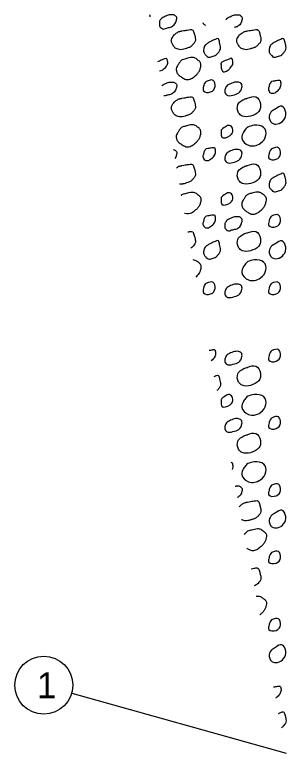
# Model space of a CAD drawing. Extents: x 0 to 340, y 0 to 220.
# Drawn here: x 135.85 to 150.51, y 109.99 to 149.82 of the extents above; entities that cross this region are included whole.
import ezdxf

# ---------------------------------------------------------------- set-up
doc = ezdxf.new("R2010")
doc.units = 0
for name, color, linetype in [('GE_P_Alignment_100_Stations', 7, 'Continuous'), ('MT_P_Work_Area', 7, 'Continuous'), ('SC_Scratch1', 7, 'Continuous')]:
    doc.layers.add(name, color=color, linetype=linetype)

msp = doc.modelspace()

# ---------------------------------------------------------------- linework, layer by layer
at = {"layer": 'GE_P_Alignment_100_Stations'}
msp.add_line((138.923, 113.234), (150.509, 109.987), dxfattribs=at)
at = {"layer": 'MT_P_Work_Area'}
msp.add_circle((137.414, 113.657), 1.567, dxfattribs=at)
at = {"layer": 'SC_Scratch1'}
for points, degree in [([(143.128, 149.812), (143.137, 149.782), (143.143, 149.748), (143.145, 149.715)], 2), ([(143.783, 149.635), (143.866, 149.676), (143.949, 149.718), (144.033, 149.76), (144.124, 149.805), (144.234, 149.814), (144.334, 149.817), (144.407, 149.819), (144.478, 149.802), (144.545, 149.736), (144.605, 149.676), (144.596, 149.596), (144.579, 149.533), (144.549, 149.428), (144.51, 149.321), (144.408, 149.236), (144.308, 149.153), (144.202, 149.141), (144.095, 149.116), (143.982, 149.09), (143.853, 149.023), (143.743, 149.122), (143.67, 149.187), (143.655, 149.263), (143.657, 149.338), (143.659, 149.404), (143.667, 149.483), (143.709, 149.538), (143.733, 149.571), (143.758, 149.602), (143.783, 149.635)], 3), ([(147.319, 149.635), (147.402, 149.676), (147.485, 149.718), (147.569, 149.76), (147.66, 149.805), (147.77, 149.814), (147.87, 149.817), (147.943, 149.819), (148.014, 149.802), (148.08, 149.736), (148.141, 149.676), (148.132, 149.596), (148.115, 149.533), (148.085, 149.428), (148.046, 149.321), (147.944, 149.236), (147.863, 149.169), (147.779, 149.148), (147.692, 149.13)], 3), ([(146.16, 149.248), (146.107, 149.265), (146.063, 149.295), (146.04, 149.341), (146.034, 149.355), (146.029, 149.369), (146.025, 149.383)], 3), ([(147.262, 149.561), (147.281, 149.585), (147.3, 149.61), (147.319, 149.635)], 2), ([(144.87, 148.945), (145.021, 148.971), (145.172, 149), (145.324, 149.021), (145.475, 149.042), (145.545, 148.783), (145.583, 148.641), (145.617, 148.512), (145.595, 148.355), (145.486, 148.235), (145.353, 148.087), (145.205, 148.03), (145.04, 147.982), (144.899, 147.941), (144.741, 147.925), (144.6, 147.985), (144.515, 148.021), (144.453, 148.083), (144.401, 148.163), (144.315, 148.297), (144.289, 148.481), (144.365, 148.608), (144.415, 148.692), (144.482, 148.766), (144.57, 148.821), (144.643, 148.868), (144.714, 148.912), (144.795, 148.93), (144.823, 148.935), (144.85, 148.941), (144.878, 148.947)], 3), ([(148.405, 148.945), (148.557, 148.971), (148.708, 149), (148.86, 149.021), (149.011, 149.042), (149.081, 148.783), (149.119, 148.641), (149.153, 148.512), (149.131, 148.355), (149.022, 148.235), (148.889, 148.087), (148.741, 148.03), (148.576, 147.982), (148.435, 147.941), (148.277, 147.925), (148.136, 147.985), (148.051, 148.021), (147.989, 148.083), (147.937, 148.163), (147.851, 148.297), (147.825, 148.481), (147.9, 148.608), (147.95, 148.692), (148.018, 148.766), (148.105, 148.821), (148.179, 148.868), (148.25, 148.912), (148.331, 148.93), (148.359, 148.935), (148.386, 148.941), (148.414, 148.947)], 3), ([(146.385, 148.363), (146.503, 148.413), (146.62, 148.463), (146.737, 148.514), (146.859, 148.566), (146.918, 148.299), (146.945, 148.175), (146.973, 148.044), (146.939, 147.897), (146.833, 147.77), (146.733, 147.651), (146.619, 147.594), (146.5, 147.558), (146.404, 147.529), (146.283, 147.524), (146.189, 147.617), (146.075, 147.73), (146.033, 147.862), (146.055, 147.976), (146.074, 148.067), (146.116, 148.187), (146.201, 148.244), (146.263, 148.284), (146.324, 148.323), (146.385, 148.363)], 3), ([(149.921, 148.363), (150.038, 148.413), (150.156, 148.463), (150.273, 148.514), (150.394, 148.566), (150.454, 148.299), (150.48, 148.175), (150.509, 148.044), (150.475, 147.897), (150.369, 147.77), (150.269, 147.651), (150.155, 147.594), (150.035, 147.558), (149.939, 147.529), (149.818, 147.524), (149.725, 147.617), (149.611, 147.73), (149.568, 147.862), (149.591, 147.976), (149.609, 148.067), (149.652, 148.187), (149.737, 148.244), (149.798, 148.284), (149.86, 148.323), (149.921, 148.363)], 3), ([(143.571, 147.3), (143.703, 147.355), (143.834, 147.41), (143.966, 147.46), (144.044, 147.49), (144.085, 147.316), (144.092, 147.242), (144.101, 147.142), (144.025, 147.038), (143.943, 146.94), (143.88, 146.864), (143.762, 146.799), (143.662, 146.785)], 3), ([(144.89, 147.394), (145.009, 147.425), (145.128, 147.456), (145.246, 147.487), (145.419, 147.532), (145.594, 147.5), (145.767, 147.355), (145.901, 147.243), (145.91, 147.077), (145.875, 146.953), (145.83, 146.796), (145.731, 146.648), (145.579, 146.518), (145.389, 146.356), (145.125, 146.292), (144.93, 146.407), (144.773, 146.5), (144.607, 146.64), (144.576, 146.805), (144.557, 146.908), (144.611, 147.028), (144.671, 147.124), (144.714, 147.192), (144.753, 147.261), (144.81, 147.316), (144.836, 147.342), (144.863, 147.368), (144.89, 147.394)], 3), ([(147.027, 147.268), (147.185, 147.332), (147.344, 147.4), (147.502, 147.46), (147.58, 147.49), (147.621, 147.316), (147.628, 147.242), (147.637, 147.142), (147.561, 147.038), (147.479, 146.94), (147.367, 146.805), (147.087, 146.708), (147.029, 146.855), (146.998, 146.934), (146.993, 147.014), (146.99, 147.095), (146.988, 147.136), (146.973, 147.18), (146.994, 147.216), (147.004, 147.235), (147.016, 147.251), (147.027, 147.268)], 3), ([(143.798, 146.012), (143.876, 146.051), (143.954, 146.09), (144.033, 146.129), (144.124, 146.175), (144.234, 146.184), (144.334, 146.187), (144.407, 146.189), (144.478, 146.171), (144.545, 146.106), (144.605, 146.046), (144.596, 145.966), (144.579, 145.902), (144.549, 145.797), (144.51, 145.691), (144.408, 145.606), (144.308, 145.523), (144.202, 145.511), (144.095, 145.486), (144.032, 145.471), (143.965, 145.444), (143.899, 145.44)], 3), ([(149.717, 146.221), (149.844, 146.239), (149.971, 146.259), (150.099, 146.277), (150.212, 146.292), (150.239, 146.047), (150.203, 145.948), (150.163, 145.84), (150.065, 145.732), (149.963, 145.654), (149.858, 145.574), (149.637, 145.587), (149.576, 145.711), (149.538, 145.789), (149.557, 145.879), (149.579, 145.957), (149.594, 146.012), (149.601, 146.075), (149.637, 146.12), (149.664, 146.154), (149.69, 146.187), (149.717, 146.221)], 3), ([(144.87, 145.315), (145.021, 145.341), (145.172, 145.37), (145.324, 145.391), (145.475, 145.412), (145.545, 145.153), (145.583, 145.011), (145.617, 144.882), (145.595, 144.724), (145.486, 144.604), (145.353, 144.457), (145.205, 144.4), (145.04, 144.352), (144.899, 144.31), (144.741, 144.295), (144.6, 144.354), (144.515, 144.39), (144.453, 144.452), (144.401, 144.532), (144.315, 144.666), (144.289, 144.851), (144.365, 144.977), (144.415, 145.061), (144.482, 145.135), (144.57, 145.191), (144.643, 145.238), (144.714, 145.282), (144.795, 145.299), (144.823, 145.305), (144.85, 145.311), (144.878, 145.317)], 3), ([(144.89, 143.763), (145.009, 143.795), (145.128, 143.826), (145.246, 143.857), (145.419, 143.901), (145.594, 143.87), (145.767, 143.725), (145.901, 143.613), (145.91, 143.446), (145.875, 143.322), (145.83, 143.166), (145.731, 143.017), (145.579, 142.887), (145.389, 142.725), (145.125, 142.661), (144.93, 142.777), (144.773, 142.87), (144.607, 143.01), (144.576, 143.175), (144.557, 143.278), (144.611, 143.397), (144.671, 143.493), (144.714, 143.562), (144.753, 143.631), (144.81, 143.686), (144.836, 143.712), (144.863, 143.738), (144.89, 143.763)], 3), ([(146.181, 142.59), (146.308, 142.609), (146.436, 142.629), (146.563, 142.646), (146.676, 142.661), (146.703, 142.416), (146.667, 142.318), (146.627, 142.209), (146.529, 142.102), (146.427, 142.024), (146.322, 141.943), (146.101, 141.957), (146.04, 142.08), (146.002, 142.158), (146.021, 142.248), (146.043, 142.326), (146.058, 142.381), (146.065, 142.444), (146.101, 142.489), (146.128, 142.523), (146.154, 142.557), (146.181, 142.59)], 3), ([(144.408, 142.55), (144.455, 142.541), (144.501, 142.518), (144.545, 142.475), (144.605, 142.415), (144.596, 142.335), (144.579, 142.272), (144.559, 142.203), (144.536, 142.133), (144.493, 142.07)], 3), ([(144.582, 141.568), (144.651, 141.612), (144.718, 141.652), (144.795, 141.669), (144.823, 141.674), (144.85, 141.68), (144.878, 141.686)], 3), ([(144.87, 141.684), (145.021, 141.71), (145.172, 141.739), (145.324, 141.76), (145.475, 141.781), (145.545, 141.522), (145.583, 141.38), (145.617, 141.251), (145.595, 141.094), (145.486, 140.974), (145.353, 140.826), (145.205, 140.769), (145.04, 140.721), (144.943, 140.693), (144.838, 140.676), (144.737, 140.688)], 3), ([(149.921, 141.102), (150.038, 141.152), (150.156, 141.202), (150.273, 141.253), (150.394, 141.305), (150.454, 141.038), (150.48, 140.914), (150.509, 140.783), (150.475, 140.636), (150.369, 140.509), (150.269, 140.39), (150.155, 140.333), (150.035, 140.297), (149.939, 140.268), (149.818, 140.263), (149.725, 140.356), (149.611, 140.469), (149.568, 140.601), (149.591, 140.715), (149.609, 140.806), (149.652, 140.926), (149.737, 140.983), (149.798, 141.024), (149.86, 141.062), (149.921, 141.102)], 3), ([(144.89, 140.133), (145.009, 140.164), (145.128, 140.195), (145.246, 140.226), (145.419, 140.271), (145.594, 140.239), (145.767, 140.094), (145.901, 139.982), (145.91, 139.816), (145.875, 139.692), (145.83, 139.535), (145.731, 139.387), (145.579, 139.257), (145.415, 139.117), (145.197, 139.051), (145.015, 139.108)], 3), ([(148.426, 140.133), (148.545, 140.164), (148.663, 140.195), (148.782, 140.226), (148.955, 140.271), (149.13, 140.239), (149.303, 140.094), (149.437, 139.982), (149.446, 139.816), (149.41, 139.692), (149.365, 139.535), (149.266, 139.387), (149.115, 139.257), (148.925, 139.095), (148.661, 139.031), (148.466, 139.146), (148.309, 139.239), (148.142, 139.379), (148.112, 139.544), (148.093, 139.647), (148.147, 139.767), (148.207, 139.863), (148.25, 139.931), (148.288, 140), (148.345, 140.055), (148.372, 140.081), (148.399, 140.107), (148.426, 140.133)], 3), ([(144.843, 140.087), (144.859, 140.102), (144.874, 140.118), (144.89, 140.133)], 2), ([(146.181, 138.96), (146.308, 138.978), (146.436, 138.998), (146.563, 139.016), (146.676, 139.031), (146.703, 138.786), (146.667, 138.687), (146.627, 138.579), (146.529, 138.471), (146.427, 138.393), (146.322, 138.313), (146.101, 138.326), (146.04, 138.45), (146.002, 138.528), (146.021, 138.618), (146.043, 138.696), (146.058, 138.751), (146.065, 138.814), (146.101, 138.859), (146.128, 138.893), (146.154, 138.926), (146.181, 138.96)], 3), ([(147.319, 138.743), (147.402, 138.785), (147.485, 138.827), (147.569, 138.868), (147.66, 138.914), (147.77, 138.923), (147.87, 138.926), (147.943, 138.928), (148.014, 138.91), (148.08, 138.845), (148.141, 138.785), (148.132, 138.705), (148.115, 138.641), (148.085, 138.536), (148.046, 138.43), (147.944, 138.345), (147.844, 138.262), (147.738, 138.25), (147.63, 138.225), (147.518, 138.199), (147.389, 138.132), (147.279, 138.231), (147.206, 138.296), (147.191, 138.372), (147.193, 138.446), (147.195, 138.513), (147.203, 138.591), (147.245, 138.646), (147.269, 138.679), (147.294, 138.711), (147.319, 138.743)], 3), ([(145.191, 138.11), (145.236, 138.117), (145.28, 138.124), (145.324, 138.13), (145.475, 138.151), (145.545, 137.892), (145.583, 137.75), (145.617, 137.621), (145.595, 137.463), (145.486, 137.343), (145.442, 137.294), (145.396, 137.255), (145.348, 137.223)], 3), ([(146.385, 137.471), (146.503, 137.522), (146.62, 137.572), (146.737, 137.622), (146.859, 137.674), (146.918, 137.408), (146.945, 137.284), (146.973, 137.153), (146.939, 137.006), (146.833, 136.879), (146.733, 136.759), (146.619, 136.703), (146.5, 136.666), (146.404, 136.637), (146.283, 136.633), (146.189, 136.726), (146.075, 136.838), (146.033, 136.97), (146.055, 137.085), (146.074, 137.176), (146.116, 137.296), (146.201, 137.352), (146.263, 137.393), (146.324, 137.432), (146.385, 137.471)], 3), ([(145.456, 136.61), (145.56, 136.597), (145.664, 136.55), (145.767, 136.464), (145.901, 136.352), (145.91, 136.185), (145.875, 136.061), (145.834, 135.92), (145.75, 135.786), (145.622, 135.666)], 3), ([(146.352, 131.724), (146.422, 131.735), (146.492, 131.745), (146.563, 131.755), (146.676, 131.77), (146.703, 131.525), (146.667, 131.426), (146.632, 131.33), (146.549, 131.233), (146.46, 131.158)], 3), ([(146.622, 130.312), (146.66, 130.328), (146.699, 130.345), (146.737, 130.361), (146.859, 130.413), (146.918, 130.147), (146.945, 130.023), (146.973, 129.892), (146.939, 129.745), (146.833, 129.618), (146.812, 129.593), (146.79, 129.57), (146.767, 129.55)], 3), ([(147.508, 125.679), (147.582, 125.699), (147.621, 125.532), (147.628, 125.459), (147.633, 125.406), (147.613, 125.351), (147.581, 125.296)], 3), ([(147.753, 124.396), (147.792, 124.401), (147.832, 124.403), (147.87, 124.404), (147.943, 124.406), (148.014, 124.389), (148.08, 124.323), (148.141, 124.263), (148.132, 124.183), (148.115, 124.12), (148.085, 124.015), (148.046, 123.908), (147.944, 123.823), (147.92, 123.803), (147.896, 123.788), (147.872, 123.775)], 3), ([(147.965, 123.286), (148.005, 123.332), (148.051, 123.374), (148.105, 123.408), (148.179, 123.455), (148.25, 123.499), (148.331, 123.516), (148.359, 123.522), (148.386, 123.528), (148.414, 123.534)], 3), ([(148.405, 123.532), (148.557, 123.558), (148.708, 123.587), (148.86, 123.608), (149.011, 123.629), (149.081, 123.37), (149.119, 123.228), (149.153, 123.099), (149.131, 122.942), (149.022, 122.821), (148.889, 122.674), (148.741, 122.617), (148.576, 122.569), (148.435, 122.527), (148.277, 122.512), (148.136, 122.571), (148.123, 122.577), (148.111, 122.583), (148.098, 122.59)], 3), ([(148.253, 121.783), (148.28, 121.826), (148.309, 121.868), (148.345, 121.903), (148.372, 121.929), (148.399, 121.955), (148.426, 121.98)], 3), ([(148.426, 121.98), (148.545, 122.012), (148.663, 122.043), (148.782, 122.074), (148.955, 122.119), (149.13, 122.087), (149.303, 121.942), (149.437, 121.83), (149.446, 121.664), (149.41, 121.54), (149.365, 121.383), (149.266, 121.234), (149.115, 121.105), (148.925, 120.942), (148.661, 120.879), (148.466, 120.994), (148.443, 121.008), (148.419, 121.023), (148.395, 121.039)], 3), ([(148.606, 119.937), (148.69, 119.951), (148.775, 119.966), (148.86, 119.977), (149.011, 119.998), (149.081, 119.739), (149.119, 119.597), (149.153, 119.468), (149.131, 119.311), (149.022, 119.191), (148.947, 119.108), (148.867, 119.053), (148.782, 119.013)], 3), ([(148.888, 118.461), (149.026, 118.47), (149.165, 118.427), (149.303, 118.312), (149.437, 118.199), (149.446, 118.033), (149.41, 117.909), (149.365, 117.752), (149.266, 117.604), (149.115, 117.474), (149.104, 117.465), (149.093, 117.456), (149.082, 117.448)], 3), ([(149.825, 113.562), (149.916, 113.576), (150.007, 113.59), (150.099, 113.602), (150.212, 113.618), (150.239, 113.372), (150.203, 113.274), (150.163, 113.166), (150.065, 113.058), (149.963, 112.98), (149.956, 112.974), (149.948, 112.969), (149.939, 112.964)], 3), ([(150.098, 112.134), (150.156, 112.159), (150.215, 112.184), (150.273, 112.209), (150.394, 112.261), (150.454, 111.994), (150.48, 111.871), (150.509, 111.74), (150.475, 111.593), (150.369, 111.466), (150.33, 111.419), (150.29, 111.383), (150.247, 111.353)], 3)]:
    msp.add_open_spline(points, degree=degree, dxfattribs=at)
for points in [[(146.181, 146.221), (146.563, 146.277), (146.667, 145.948), (146.427, 145.654), (146.04, 145.711), (146.043, 145.957), (146.101, 146.12), (146.181, 146.221)], [(147.319, 146.004), (147.569, 146.129), (147.87, 146.187), (148.08, 146.106), (148.115, 145.902), (147.944, 145.606), (147.63, 145.486), (147.279, 145.492), (147.193, 145.707), (147.245, 145.907), (147.319, 146.004)], [(148.405, 145.315), (148.86, 145.391), (149.119, 145.011), (149.022, 144.604), (148.576, 144.352), (148.136, 144.354), (147.937, 144.532), (147.9, 144.977), (148.105, 145.191), (148.331, 145.299), (148.414, 145.317)], [(149.921, 144.732), (150.273, 144.883), (150.48, 144.545), (150.369, 144.14), (150.035, 143.927), (149.725, 143.987), (149.591, 144.346), (149.737, 144.613), (149.921, 144.732)], [(147.027, 143.637), (147.502, 143.83), (147.628, 143.612), (147.479, 143.309), (147.029, 143.225), (146.99, 143.465), (146.994, 143.586), (147.027, 143.637)], [(148.426, 143.763), (148.782, 143.857), (149.303, 143.725), (149.41, 143.322), (149.115, 142.887), (148.466, 142.777), (148.112, 143.175), (148.207, 143.493), (148.345, 143.686), (148.426, 143.763)], [(149.717, 142.59), (150.099, 142.646), (150.203, 142.318), (149.963, 142.024), (149.576, 142.08), (149.579, 142.326), (149.637, 142.489), (149.717, 142.59)], [(147.319, 142.374), (147.569, 142.499), (147.87, 142.556), (148.08, 142.475), (148.115, 142.272), (147.944, 141.975), (147.63, 141.855), (147.279, 141.861), (147.193, 142.077), (147.245, 142.277), (147.319, 142.374)], [(148.405, 141.684), (148.86, 141.76), (149.119, 141.38), (149.022, 140.974), (148.576, 140.721), (148.136, 140.724), (147.937, 140.902), (147.9, 141.347), (148.105, 141.56), (148.331, 141.669), (148.414, 141.686)], [(147.027, 140.007), (147.502, 140.199), (147.628, 139.981), (147.479, 139.679), (147.029, 139.594), (146.99, 139.834), (146.994, 139.955), (147.027, 140.007)], [(149.717, 138.96), (150.099, 139.016), (150.203, 138.687), (149.963, 138.393), (149.576, 138.45), (149.579, 138.696), (149.637, 138.859), (149.717, 138.96)], [(148.405, 138.054), (148.86, 138.13), (149.119, 137.75), (149.022, 137.343), (148.576, 137.091), (148.136, 137.093), (147.937, 137.271), (147.9, 137.716), (148.105, 137.93), (148.331, 138.038), (148.414, 138.056)], [(149.921, 137.471), (150.273, 137.622), (150.48, 137.284), (150.369, 136.879), (150.035, 136.666), (149.725, 136.726), (149.591, 137.085), (149.737, 137.352), (149.921, 137.471)], [(148.426, 136.502), (148.782, 136.596), (149.303, 136.464), (149.41, 136.061), (149.115, 135.626), (148.466, 135.516), (148.112, 135.914), (148.207, 136.232), (148.345, 136.425), (148.426, 136.502)], [(146.181, 135.329), (146.563, 135.385), (146.667, 135.057), (146.427, 134.763), (146.04, 134.819), (146.043, 135.065), (146.101, 135.228), (146.181, 135.329)], [(149.717, 135.329), (150.099, 135.385), (150.203, 135.057), (149.963, 134.763), (149.576, 134.819), (149.579, 135.065), (149.637, 135.228), (149.717, 135.329)], [(147.319, 135.113), (147.569, 135.238), (147.87, 135.295), (148.08, 135.214), (148.115, 135.011), (147.944, 134.714), (147.63, 134.594), (147.279, 134.6), (147.193, 134.816), (147.245, 135.016), (147.319, 135.113)], [(147.319, 131.482), (147.569, 131.607), (147.87, 131.665), (148.08, 131.584), (148.115, 131.38), (147.944, 131.084), (147.63, 130.964), (147.279, 130.97), (147.193, 131.185), (147.245, 131.385), (147.319, 131.482)], [(149.717, 131.699), (150.099, 131.755), (150.203, 131.426), (149.963, 131.132), (149.576, 131.189), (149.579, 131.435), (149.637, 131.598), (149.717, 131.699)], [(148.405, 130.793), (148.86, 130.869), (149.119, 130.489), (149.022, 130.082), (148.576, 129.83), (148.136, 129.832), (147.937, 130.01), (147.9, 130.455), (148.105, 130.669), (148.331, 130.777), (148.414, 130.795)], [(147.027, 129.115), (147.502, 129.308), (147.628, 129.09), (147.479, 128.787), (147.029, 128.703), (146.99, 128.943), (146.994, 129.064), (147.027, 129.115)], [(148.426, 129.241), (148.782, 129.335), (149.303, 129.203), (149.41, 128.8), (149.115, 128.365), (148.466, 128.255), (148.112, 128.653), (148.207, 128.971), (148.345, 129.164), (148.426, 129.241)], [(147.319, 127.852), (147.569, 127.977), (147.87, 128.034), (148.08, 127.953), (148.115, 127.75), (147.944, 127.453), (147.63, 127.333), (147.279, 127.339), (147.193, 127.555), (147.245, 127.755), (147.319, 127.852)], [(149.717, 128.068), (150.099, 128.124), (150.203, 127.796), (149.963, 127.502), (149.576, 127.558), (149.579, 127.804), (149.637, 127.967), (149.717, 128.068)], [(148.405, 127.162), (148.86, 127.238), (149.119, 126.858), (149.022, 126.452), (148.576, 126.199), (148.136, 126.202), (147.937, 126.38), (147.9, 126.825), (148.105, 127.038), (148.331, 127.147), (148.414, 127.164)], [(148.426, 125.611), (148.782, 125.704), (149.303, 125.572), (149.41, 125.17), (149.115, 124.735), (148.466, 124.624), (148.112, 125.022), (148.207, 125.341), (148.345, 125.533), (148.426, 125.611)], [(149.717, 124.438), (150.099, 124.494), (150.203, 124.165), (149.963, 123.871), (149.576, 123.928), (149.579, 124.174), (149.637, 124.337), (149.717, 124.438)], [(149.921, 122.95), (150.273, 123.1), (150.48, 122.762), (150.369, 122.357), (150.035, 122.145), (149.725, 122.204), (149.591, 122.563), (149.737, 122.83), (149.921, 122.95)], [(149.717, 120.807), (150.099, 120.863), (150.203, 120.535), (149.963, 120.241), (149.576, 120.297), (149.579, 120.543), (149.637, 120.707), (149.717, 120.807)], [(149.717, 117.177), (150.099, 117.233), (150.203, 116.904), (149.963, 116.61), (149.576, 116.667), (149.579, 116.913), (149.637, 117.076), (149.717, 117.177)], [(149.921, 115.689), (150.273, 115.839), (150.48, 115.501), (150.369, 115.096), (150.035, 114.884), (149.725, 114.943), (149.591, 115.302), (149.737, 115.569), (149.921, 115.689)]]:
    msp.add_spline(points, degree=3, dxfattribs=at)

# ---------------------------------------------------------------- texts
at = {"layer": 'MT_P_Work_Area'}
msp.add_text('1', height=1.4, dxfattribs=at).set_placement((137.05, 112.957))

doc.saveas('drawing.dxf')
